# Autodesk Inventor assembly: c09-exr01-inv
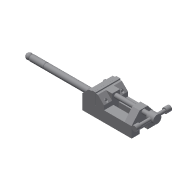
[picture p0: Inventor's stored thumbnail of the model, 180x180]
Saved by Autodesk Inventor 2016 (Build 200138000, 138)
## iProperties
Created: 2011-07
Part Number: c09-exr01-inv
Document SubType Name: Assembly
Designer: CadCim
Author: CadCim
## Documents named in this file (9)
- D:\KAVITA\Autodesk Inventor_2015_By Avijeet\Inventor_psrtfiles_2015\Inventor_2015_Exr\c09_Inv_2015_Exr\c09_Inv\c09_exr01_inv\Drill Press Vice\c09-exr01-inv.iam
- D:\KAVITA\Autodesk Inventor_2015_By Avijeet\Inventor_psrtfiles_2015\Inventor_2015_Exr\c09_Inv_2015_Exr\c09_Inv\c09_exr01_inv\Drill Press Vice\Base.ipt
- D:\KAVITA\Autodesk Inventor_2015_By Avijeet\Inventor_psrtfiles_2015\Inventor_2015_Exr\c09_Inv_2015_Exr\c09_Inv\c09_exr01_inv\Drill Press Vice\Jaw Face.ipt
- D:\KAVITA\Autodesk Inventor_2015_By Avijeet\Inventor_psrtfiles_2015\Inventor_2015_Exr\c09_Inv_2015_Exr\c09_Inv\c09_exr01_inv\Drill Press Vice\Movable Jaw.ipt
- D:\KAVITA\Autodesk Inventor_2015_By Avijeet\Inventor_psrtfiles_2015\Inventor_2015_Exr\c09_Inv_2015_Exr\c09_Inv\c09_exr01_inv\Drill Press Vice\Safety Handle.ipt
- D:\KAVITA\Autodesk Inventor_2015_By Avijeet\Inventor_psrtfiles_2015\Inventor_2015_Exr\c09_Inv_2015_Exr\c09_Inv\c09_exr01_inv\Drill Press Vice\Clamp Screw.ipt
- D:\KAVITA\Autodesk Inventor_2015_By Avijeet\Inventor_psrtfiles_2015\Inventor_2015_Exr\c09_Inv_2015_Exr\c09_Inv\c09_exr01_inv\Drill Press Vice\Clamp Screw Handle.ipt
- D:\KAVITA\Autodesk Inventor_2015_By Avijeet\Inventor_psrtfiles_2015\Inventor_2015_Exr\c09_Inv_2015_Exr\c09_Inv\c09_exr01_inv\Drill Press Vice\Handle Stop.ipt
- D:\KAVITA\Autodesk Inventor_2015_By Avijeet\Inventor_psrtfiles_2015\Inventor_2015_Exr\c09_Inv_2015_Exr\c09_Inv\c09_exr01_inv\Drill Press Vice\Cap Screw.ipt
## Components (13 placed, 8 different names)
1. Base:1 — Insert:1, Insert:2, Insert:3, Insert:9, Insert:10
2. Jaw Face:1 — Insert:1, Insert:2, Mate:1, Mate:2, Mate:5, Mate:7
3. Movable Jaw:1 — Mate:1, Mate:2, Mate:3, Insert:4, Insert:5, Insert:6, Insert:11, Insert:12
4. Safety Handle:1 — Insert:3
5. Clamp Screw:1 — Mate:3, Insert:4, Mate:4, Mate:6
6. Clamp Screw Handle:1 — Mate:4, Insert:7, Insert:8
7. Jaw Face:2 — Insert:5, Insert:6, Mate:5, Mate:7
8. Handle Stop:1 — Insert:7, Mate:6
9. Handle Stop:2 — Insert:8
10. Cap Screw:1 — Insert:12
11. Cap Screw:2 — Insert:11
12. Cap Screw:3 — Insert:10
13. Cap Screw:4 — Insert:9
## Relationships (19: Insert 12, Mate 7)
- Insert:1: Base:1 ↔ Jaw Face:1
- Insert:2: Base:1 ↔ Jaw Face:1
- Mate:1: Jaw Face:1 ↔ Movable Jaw:1
- Mate:2: Jaw Face:1 ↔ Movable Jaw:1
- Insert:3: Base:1 ↔ Safety Handle:1
- Mate:3: Movable Jaw:1 ↔ Clamp Screw:1
- Insert:4: Movable Jaw:1 ↔ Clamp Screw:1
- Mate:4: Clamp Screw:1 ↔ Clamp Screw Handle:1
- Insert:5: Movable Jaw:1 ↔ Jaw Face:2
- Insert:6: Movable Jaw:1 ↔ Jaw Face:2
- Mate:5: Jaw Face:1 ↔ Jaw Face:2
- Insert:7: Clamp Screw Handle:1 ↔ Handle Stop:1
- Insert:8: Clamp Screw Handle:1 ↔ Handle Stop:2
- Mate:6: Clamp Screw:1 ↔ Handle Stop:1
- Insert:9: Base:1 ↔ Cap Screw:4
- Insert:10: Base:1 ↔ Cap Screw:3
- Insert:11: Movable Jaw:1 ↔ Cap Screw:2
- Insert:12: Movable Jaw:1 ↔ Cap Screw:1
- Mate:7: Jaw Face:1 ↔ Jaw Face:2
